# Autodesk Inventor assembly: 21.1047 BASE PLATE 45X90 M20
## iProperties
Created: 2007-03
Part Number: 21.1047 BASE PLATE 45X90 M20
Document SubType Name: Assembly
Designer: Andy Moles
Author: Andy Moles
